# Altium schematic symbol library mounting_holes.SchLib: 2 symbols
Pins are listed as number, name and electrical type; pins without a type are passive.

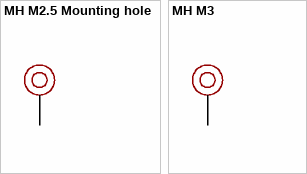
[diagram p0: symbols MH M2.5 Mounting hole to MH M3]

## MH M2.5 Mounting hole
designator MH?, comment M2.5  (value not drawn)  (no BOM)
Mounting Hole M2.5 for mPCIe
footprint MH mPCIe M2.5 (M2.5 mounting hole for mPCIe boards)
pins: 1

## MH M3
designator MH?, comment M3  (value not drawn)  (no BOM)
footprint MH Cubesat M3
pins: 1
